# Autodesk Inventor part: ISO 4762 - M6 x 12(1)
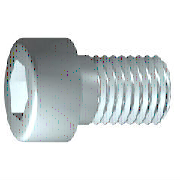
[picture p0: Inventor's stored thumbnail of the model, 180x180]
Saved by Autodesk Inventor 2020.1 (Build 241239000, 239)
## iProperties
Created: 2019-01
Part Number: ISO 4762 - M6 x 12(1)
Material: Edelstahl, 440C
Description: Innensechskantschraube
Document SubType Name: Modeling
Standard: ISO 4762
Designer: lutzd
Standard Revision: Fourth edition 2004-03-01
Standards Organization: ISO
Language: de-DE
Size Designation: M6 x 12
Categories: <MemberInstance><Categories><Category DisplayName="Verbindungselemente" InternalName="e4da775c-781d-43d5-af7c-5136215cf5a6" Mnemonic="FSTN"><Category DisplayNam
Mass: 5.62501 g
Surface Area: 6.13303 cm^2
Volume: 0.725807 cm^3
Density: 7.75 g/cm^3
Appearance: Halbpoliert
IsCustomPart: 0
Author: lutzd
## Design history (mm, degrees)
body "Solid1"
sketch "Skizze1"
  geometry: L1 (-1.333, 0)-(12, 0); L2 (12, 0)-(12, 3); L3 (12, 3)-(2.5, 3); L4 (2.5, 3)-(1.886, 3); L5 (1.886, 3)-(0, 3); L6 (0, 3)-(0, 5); L7 (0, 5)-(-6, 5); L8 (-6, 5)-(-6, 2.887); L9 (-6, 2.887)-(-3, 2.887); L10 (-3, 2.887)-(-1.333, 0); L11 (-9.6, 0)-(15.6, 0) reference; L12 (0, -1)-(0, 6) reference; L13 (2.5, 3)-(0, 3)
  constraints: 22 end point, 6 parallel, 2 collinear, 2 perpendicular, 1 horizontal, 1 point on line
  dimensions: "d1" = 9.5 distance from line of L3.end L2 (= GEL); "d2" = 0.61355 distance of L4.end L3.end (computed from GAL); "d3" = 6 distance between parallel lines of L8 L6 (= KOH); "d4" = 3 distance of L8.end L9.end (= INTI); "d5" = 60 deg angle of L10 L1; "d6" = 6 diameter of L3 L1 (= GD); "d7" = 6 diameter of L5 L1 (= BDM); "d8" = 5.7735 diameter of L9 L1 (= 1.1547 x SW); "d9" = 10 diameter of L7 L1 (= KOD); "d26" = 12 distance between parallel lines of L12 L2 (= NLG)
workplane "Work Plane1"
fillet "Fillet2" dims "d30" = 0.1 (= R)
revolve "Körper" stored, may be unused: angle "d10" = 90 deg
sketch "Skizze2"
  geometry: L1 (0, -7)-(0, 7) reference; L2 (-7, 0)-(7, 0) reference; L3 (2.887, 0)-(1.443, -2.5); L4 (1.443, -2.5)-(-1.443, -2.5); L5 (-1.443, -2.5)-(-2.887, 0); L6 (-2.887, 0)-(-1.443, 2.5); L7 (-1.443, 2.5)-(1.443, 2.5); L8 (1.443, 2.5)-(2.887, 0); 2 further points
  constraints: 12 end point, 1 coincident, 1 horizontal alignment, 1 point on line, 12 other
extrude "Loch" join sketch "Skizze2" stored distance "d11" = 10; taper "d12" = 0 deg
fillet "Rundung1" dims "d17" = 0.6 (= RR)
feature "Gewinde" dims "d13" = 9.5 (= GEL), "d14" = 0
chamfer "Fase1" distance "d15" = 0.61345 (= -0.5 x SPD + 0.5 x GD); stored, may be unused: second distance "d16" = 0.61345 (= GUL), angle "d27" = 45 deg
other parameters: "GD" = 6 [user parameter; used in 2 equation terms], "NLG" = 12 [user parameter; used in 1 equation term], "GEL" = 9.5 [user parameter; used in 2 equation terms], "KOD" = 10 [user parameter; used in 1 equation term], "KOH" = 6 [user parameter; used in 1 equation term], "INTI" = 3 [user parameter; used in 1 equation term], "GAL" = 0.61345 (= 0.61345 x PTC) [user parameter; used in 1 equation term], "GUL" = 0.61345 (= 0.61345 x PTC) [user parameter; used in 1 equation term], "BDM" = 6 (= NND) [user parameter; used in 1 equation term], "SW" = 5 [user parameter; used in 2 equation terms], "RR" = 0.6 [user parameter; used in 1 equation term], "SPD" = 4.7731 (= NND - 1.2269 x PTC) [user parameter; used in 1 equation term], "d19" = 0, "d28" = 0, "d29" = 0, "R" = 0.1 [user parameter; used in 1 equation term], "TOA" = 30 deg [user parameter], "GD1" = 4.7731 (= THREADDIA - 1.2269 x PTC) [user parameter], "THREADDIA" = 6 [user parameter; used in 1 equation term], "FAWI" = 45 deg [user parameter], "PTC" = 1 [user parameter; used in 5 equation terms], "NND" = 6 [user parameter; used in 2 equation terms], "E0" = 5.775 (= 1.155 x SW) [user parameter]
